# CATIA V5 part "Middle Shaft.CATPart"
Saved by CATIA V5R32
Part number: Middle shaft
Bounding box of the stored display mesh (mm): x 0 to 100, y -25 to 25, z -24.818 to 24.818
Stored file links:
  D:\PROJECTS\Project 2022\CATIA V5 6R 2022\Resources\Part Files\c16_catia_v5_6r2022_prt\CV Joint-(Fig16-51)\Middle Shaft.CATPart
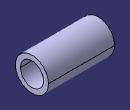
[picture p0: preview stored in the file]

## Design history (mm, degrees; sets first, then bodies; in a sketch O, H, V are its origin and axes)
Body1 (main body)
  Sketch1 on yz-plane, origin (0, 0, 0), H (0, 1, 0), V (0, 0, 1)
    circle A1 centre (0, 0) radius 25
    circle A2 centre (0, 0) radius 17.5
    radius A1 = 25
    radius A2 = 17.5
  Pad1: profile Sketch1, direction (1, 0, 0), length 100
